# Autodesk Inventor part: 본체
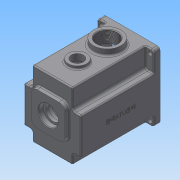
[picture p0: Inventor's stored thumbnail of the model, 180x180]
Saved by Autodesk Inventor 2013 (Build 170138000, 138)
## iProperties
Created: 2016-02
Part Number: 본체
Material: 알루미늄 6061
Document SubType Name: Modeling
Designer: mduedu
Density: 2.71 g/cm^3
Author: mduedu
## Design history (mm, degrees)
sketch "스케치1"
  geometry: L1 (-47, -47)-(47, -47); L2 (47, -47)-(47, 63); L3 (47, 63)-(-47, 63); L4 (-47, 63)-(-47, -47); 2 further points
  constraints: 8 end point, 2 parallel, 1 horizontal, 1 midpoint, 1 perpendicular, 1 vertical alignment
  dimensions: "d0" = 94 distance of L2.end L3.end; "d155" = 110 distance of L1.end L2.end; "d156" = 47 distance from line of L1 point (0, 0)
extrude "돌출1" new body sketch "스케치1" distance "d2" = 130; taper "d3" = 0 deg
sketch "스케치3"
  geometry: C1 r 40 at (0, 0); 1 further point
  constraints: 1 centre point, 1 coincident
  dimensions: "d9" = 80 diameter of C1
extrude "돌출3" cut sketch "스케치3" distance "d11" = 121; taper "d12" = 0 deg
sketch "스케치4"
  geometry: C1 r 21 at (0, 11); 1 further point
  constraints: 1 centre point, 1 vertical alignment
  dimensions: "d13" = 21 radius of C1; "d15" = 11 distance of point (0, 0) C1.centre
extrude "돌출4" join sketch "스케치4" distance "d16" = 7; taper "d17" = 0 deg
sketch "스케치5"
  geometry: C1 r 15 at (0, -20); 1 further point
  constraints: 1 centre point, 1 vertical alignment
  dimensions: "d18" = 15 radius of C1; "d20" = 20 distance of point (0, 0) C1.centre
extrude "돌출5" join sketch "스케치5" distance "d21" = 7; taper "d22" = 0 deg
sketch "스케치6"
  geometry: L1 (-28, -17)-(28, -17); L2 (28, -17)-(28, 39); L3 (28, 39)-(-28, 39); L4 (-28, 39)-(-28, -17); L5 (-28, -17)-(28, 39); L6 (28, -17)-(-28, 39); C1 r 28 at (0, 11); A1 r 21 centre (0, 11) between (8.978, -7.984) and (-8.978, -7.984) reference; 1 further point
  constraints: 12 end point, 2 midpoint, 2 parallel, 2 tangent, 1 centre point, 1 coincident, 1 horizontal, 1 perpendicular
  dimensions: "d23" = 56 diameter of C1
extrude "돌출6" join sketch "스케치6" distance "d25" = 7; taper "d26" = -3 deg
hole "구멍1" diameter "d29" = 35; stored, may be unused: countersink angle "d33" = 90 deg, drill point angle "d35" = 0 deg; dims "d27" = 10, "d28" = 10, "d30" = 6, "d31" = 4, "d32" = 2, "d34" = 10
hole "구멍2" diameter "d38" = 22; stored, may be unused: countersink angle "d42" = 90 deg, drill point angle "d44" = 0 deg; dims "d36" = 10, "d37" = 10, "d39" = 6, "d40" = 4, "d41" = 2, "d43" = 7
hole "구멍3" diameter "d47" = 19; stored, may be unused: countersink angle "d51" = 90 deg, drill point angle "d53" = 0 deg; dims "d45" = 10, "d46" = 10, "d48" = 6, "d49" = 4, "d50" = 2, "d52" = 1
hole "구멍4" diameter "d56" = 32; stored, may be unused: countersink angle "d60" = 90 deg, drill point angle "d62" = 0 deg; dims "d57" = 6, "d58" = 4, "d59" = 2, "d61" = 8, "d220" = 10, "d221" = 10
hole "구멍5" diameter "d65" = 25; stored, may be unused: countersink angle "d69" = 90 deg, drill point angle "d71" = 0 deg; dims "d63" = 10, "d64" = 10, "d66" = 6, "d67" = 4, "d68" = 2, "d70" = 8
fillet "모깎기2" dims "d73" = 0.3
fillet "모깎기3" dims "d74" = 2
chamfer "모따기1" distance "d75" = 1; stored, may be unused: second distance "d76" = 2, angle "d77" = 45 deg
fillet "모깎기4" dims "d78" = 3
sketch "스케치16"
  geometry: L1 (-23, 32.726)-(23, 32.726); L2 (23, 32.726)-(23, 53); L3 (23, 53)-(-23, 53); L4 (-23, 53)-(-23, 32.726); L5 (-47, 63)-(47, 63) reference; 3 further points
  constraints: 8 end point, 2 parallel, 1 horizontal, 1 midpoint, 1 perpendicular, 1 vertical alignment, 2 other
  dimensions: "d160" = 46 distance of L2.end L3.end; "d163" = 10 distance between parallel lines of L3 L5
extrude "돌출15" cut sketch "스케치16" stored distance "d164" = 10; taper "d165" = 0 deg
fillet "모깎기5" dims "d79" = 2
fillet "모깎기15" dims "d166" = 5
sketch "스케치7"
  geometry: L1 (-23, 48)-(-23, 35.228) reference; L2 (23, 35.228)-(23, 48) reference; L3 (18, 53)-(-18, 53) reference; L4 (47, 63)-(47, -47) reference; L5 (47, -47)-(-47, -47) reference; L6 (-47, -47)-(-47, 63) reference; L7 (-47, 63)-(47, 63) reference; L8 (-26, 48)-(-26, 35.228); L9 (26, 35.228)-(26, 48); L10 (18, 56)-(-18, 56); C1 r 43 at (0, 0); A1 r 5 centre (-18, 48) between (-18, 53) and (-23, 48) reference; A2 r 5 centre (-28, 35.228) between (-24.889, 31.314) and (-23, 35.228) reference; A3 r 40 centre (0, 0) between (-24.889, 31.314) and (24.889, 31.314) reference; A4 r 5 centre (28, 35.228) between (23, 35.228) and (24.889, 31.314) reference; A5 r 5 centre (18, 48) between (23, 48) and (18, 53) reference; A6 r 8 centre (-18, 48) between (-18, 56) and (-26, 48); A7 r 2 centre (-28, 35.228) between (-26.756, 33.662) and (-26, 35.228); A8 r 43 centre (0, 0) between (-26.756, 33.662) and (26.756, 33.662); A9 r 2 centre (28, 35.228) between (26, 35.228) and (26.756, 33.662); A10 r 8 centre (18, 48) between (26, 48) and (18, 56); 1 further point
  constraints: 10 point on circle, 6 centre point, 6 end point, 1 coincident, 7 other
  dimensions: "d80" = 86 diameter of C1; "d167" = 3 distance between parallel lines of L3 L10
extrude "돌출7" cut sketch "스케치7" distance "d83" = 9; taper "d84" = 0 deg
sketch "스케치8" dims "d168" = 36
  geometry: L1 (-36, 4)-(-39.799, 4); L2 (-36, -4)-(-39.799, -4); A1 r 4 centre (-36, 0) between (-36, 4) and (-36, -4); A2 r 40 centre (0, 0) between (-24.889, 31.314) and (24.889, 31.314) reference; A3 r 40 centre (0, 0) between (-39.799, 4) and (-39.799, -4); 2 further points
  constraints: 5 point on circle, 4 end point, 2 centre point, 2 coincident, 2 horizontal alignment, 2 tangent, 1 horizontal, 1 parallel, 2 other
  dimensions: "d169" = 4 radius of A1
extrude "돌출9" join sketch "스케치8" stored distance "d89" = 9; taper "d90" = 0 deg
fillet "모깎기6" dims "d91" = 3.5
node "작업 평면1"
sketch "스케치9"
  geometry: L1 (47, 63)-(33, 63); L2 (33, 63)-(33, 30); L3 (33, 30)-(47, 30); L4 (47, 30)-(47, 63); L5 (47, 63)-(-47, 63) reference; L6 (47, -47)-(47, 63) reference; A1 r 40 centre (0, 0) between (-39.148, -8.214) and (39.148, -8.214) reference; 1 further point
  constraints: 8 end point, 2 parallel, 1 coincident, 1 horizontal, 1 perpendicular
  dimensions: "d95" = 33 distance from line of L2 point (0, 0); "d96" = 30 distance from line of L3 point (0, 0)
extrude "돌출10" cut sketch "스케치9" distance "d97" = 110; taper "d98" = 0 deg
extrude "돌출21" cut sketch "스케치9" stored distance "d217" = 10; taper "d218" = 0 deg
sketch "스케치11" dims "d20" = 20
  geometry: L1 (-40, -40)-(40, -40); L2 (40, -40)-(40, 56); L3 (40, 56)-(-40, 56); L4 (-40, 56)-(-40, -40); L5 (-47, -47)-(47, -47) reference; L6 (47, 63)-(-47, 63) reference; L7 (-47, 63)-(-47, -47) reference; C1 r 3.5 at (-40, 56); C2 r 3.5 at (40, 56); C3 r 3.5 at (40, -40); C4 r 3.5 at (-40, -40); 1 further point
  constraints: 8 end point, 4 centre point, 4 coincident, 3 equal radius, 2 parallel, 1 horizontal, 1 perpendicular
  dimensions: "d109" = 80 distance of L2.end L3.end; "d112" = 7 diameter of C1; "d157" = 7 distance from line of L1.start L5; "d158" = 7 distance between parallel lines of L6 L3; "d159" = 7 distance from line of L7 L3.end
extrude "돌출12" cut sketch "스케치11" stored distance "d113" = 63; taper "d114" = 0 deg
fillet "모깎기7" dims "d115" = 5, "d187" = 5
fillet "모깎기8" dims "d116" = 5
fillet "모깎기18" dims "d219" = 2
fillet "모깎기12" dims "d120" = 2
fillet "모깎기13" dims "d121" = 2
sketch "스케치12"
  geometry: 3 further points
  constraints: 2 horizontal alignment
hole "구멍6" sketch "스케치12" at (36, 0), (-36, 0) diameter "d122" = 3.242; stored, may be unused: countersink angle "d126" = 90 deg, drill point angle "d128" = 120 deg; dims "d123" = 7, "d124" = 4, "d125" = 2, "d127" = 9
fillet "모깎기14" dims "d147" = 10
chamfer "모따기4" distance "d151" = 1; stored, may be unused: second distance "d152" = 2, angle "d153" = 45 deg
sketch "스케치20"
  geometry: L1 (73, -12)-(73, -130) reference; L2 (84, -8)-(77, -8) reference; L3 (84, 0)-(84, -8) reference; L4 (84, 0)-(0, 0) reference; L5 (7, -8)-(0, -8) reference; L6 (11, -130)-(11, -12) reference; L7 (0, -8)-(0, 0) reference; L8 (73, -130)-(11, -130) reference; L9 (42, 0)-(42, -130); C1 r 10 at (42, -89); A1 r 4 centre (77, -12) between (77, -8) and (73, -12) reference; A2 r 4 centre (7, -12) between (11, -12) and (7, -8) reference
  constraints: 2 end point, 1 centre point, 1 midpoint, 1 point on line
  dimensions: "d189" = 20 diameter of C1; "d190" = 41 distance from line of C1.centre L8
extrude "돌출19" cut sketch "스케치20" stored distance "d191" = 10; taper "d192" = 0 deg
sketch "스케치18"
  geometry: C1 r 15 at (42, -89); C2 r 10 at (42, -89) reference; 1 further point
  constraints: 1 centre point, 1 concentric
  dimensions: "d174" = 30 diameter of C1
extrude "돌출17" join sketch "스케치18" distance "d175" = 5; taper "d176" = 0 deg
fillet "모깎기16" dims "d177" = 2
sketch "스케치19"
  geometry: C1 r 10 at (18, 80) reference; C2 r 15 at (18, 80); 1 further point
  constraints: 1 centre point, 1 coincident
  dimensions: "d178" = 30 diameter of C2
extrude "돌출18" cut sketch "스케치19" distance "d181" = 5; taper "d182" = 0 deg
chamfer "모따기5" distance "d183" = 0.5; stored, may be unused: second distance "d184" = 2, angle "d185" = 45 deg
sketch "스케치21"
  geometry: L1 (-12, 14)-(-130, 14) reference; L2 (-8, 0)-(-8, 10) reference; L3 (0, 0)-(0, 100) reference; L4 (-8, 100)-(0, 100) reference; L5 (-8, 74)-(-8, 100) reference; L6 (-130, 70)-(-12, 70) reference; L7 (-130, 14)-(-130, 70) reference; L8 (0, 0)-(-8, 0) reference; L9 (-130, 14)-(-130, 70) reference; L10 (27.4, 42)-(-164.4, 42) reference; A1 r 4 centre (-12, 74) between (-12, 70) and (-8, 74) reference; A2 r 4 centre (-12, 10) between (-8, 10) and (-12, 14) reference; 3 further points
  constraints: 1 coincident, 1 point on line, 1 other
  dimensions: "d222" = 65 distance from line of point (-65, 42) L9
feature "엠보싱2" sketch "스케치21" dims "d20" = 20, "d193" = 0.5, "d194" = 0
sketch "스케치22"
  geometry: L1 (73, -12)-(73, -130) reference; L2 (84, -8)-(77, -8) reference; L3 (84, 0)-(84, -8) reference; L4 (84, 0)-(0, 0) reference; L5 (7, -8)-(0, -8) reference; L6 (11, -130)-(11, -12) reference; L7 (0, -8)-(0, 0) reference; L8 (73, -130)-(11, -130) reference; L9 (42, -130)-(42, 0); C1 r 17 at (42, -89) reference; C2 r 22.5 at (42, -40); A1 r 4 centre (77, -12) between (77, -8) and (73, -12) reference; A2 r 4 centre (7, -12) between (11, -12) and (7, -8) reference
  constraints: 2 end point, 1 centre point, 1 midpoint, 1 point on line
  dimensions: "d195" = 45 diameter of C2; "d197" = 40 distance from line of C2.centre L4
extrude "돌출20" join sketch "스케치22" distance "d198" = 10; taper "d199" = 0 deg
fillet "모깎기17" dims "d200" = 3
hole "구멍7" diameter "d203" = 33.376; stored, may be unused: countersink angle "d207" = 90 deg, drill point angle "d209" = 118 deg; dims "d204" = 6, "d205" = 4, "d206" = 2, "d208" = 8, "d223" = 10, "d224" = 10
chamfer "모따기6" distance "d210" = 1; stored, may be unused: second distance "d211" = 2, angle "d212" = 45 deg
fillet "모깎기19" dims "d225" = 2
node "솔리드1"
pattern_circular "원형 패턴1" dims angle "d93" = 360 deg
mirror "대칭1"
mirror "대칭2"
node "투영된 루프1"
node "투영된 루프2"
node "투영된 루프3"
node "절단 모서리 투영3"
